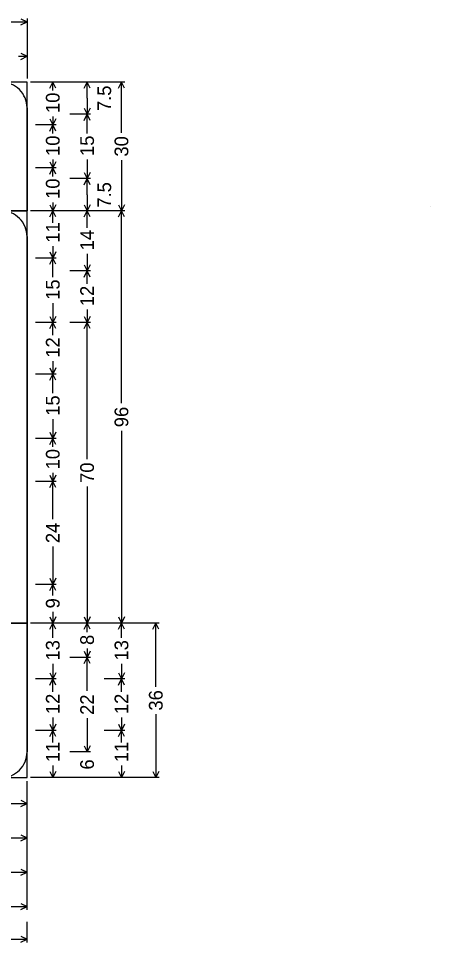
# Model space of a CAD drawing. Extents: x 667331 to 731245, y 738830 to 753817.
# Drawn here: x 720112.7 to 720256.7, y 747275.8 to 747598.6 of the extents above; entities that cross this region are included whole.
import ezdxf

# ---------------------------------------------------------------- set-up
doc = ezdxf.new("R2010")
doc.units = 0
doc.layers.add('R_SIGN', color=7, linetype='Continuous')

msp = doc.modelspace()

# ---------------------------------------------------------------- linework, layer by layer
at = {"layer": 'R_SIGN'}
for p, q in [((720113.54, 747598.51), (720115.68, 747597.43)), ((720115.68, 747598.63), (720115.68, 747577.63)), ((720027.67, 747597.43), (720115.68, 747597.43)), ((720113.54, 747596.36), (720115.68, 747597.43)), ((720112.71, 747585.43), (720115.68, 747585.43)), ((720113.54, 747586.51), (720115.68, 747585.43)), ((720113.54, 747584.36), (720115.68, 747585.43)), ((720115.68, 747586.63), (720115.68, 747579.43)), ((720149.88, 747576.43), (720116.88, 747576.43)), ((720125.88, 747576.43), (720118.68, 747576.43)), ((720123.61, 747574.29), (720124.68, 747576.43)), ((720124.68, 747573.46), (720124.68, 747576.43)), ((720125.76, 747574.29), (720124.68, 747576.43)), ((720137.88, 747576.43), (720130.68, 747576.43)), ((720135.61, 747574.29), (720136.68, 747576.43)), ((720136.68, 747570.81), (720136.68, 747576.43)), ((720137.76, 747574.29), (720136.68, 747576.43)), ((720147.61, 747574.29), (720148.68, 747576.43)), ((720148.68, 747558.68), (720148.68, 747576.43)), ((720149.76, 747574.29), (720148.68, 747576.43)), ((720136.68, 747570.81), (720136.68, 747565.18)), ((720135.61, 747567.33), (720136.68, 747565.18)), ((720137.76, 747567.33), (720136.68, 747565.18)), ((720123.61, 747563.58), (720124.68, 747561.43)), ((720124.68, 747564.4), (720124.68, 747561.43)), ((720125.76, 747563.58), (720124.68, 747561.43)), ((720137.88, 747565.18), (720130.68, 747565.18)), ((720135.61, 747563.04), (720136.68, 747565.18)), ((720136.68, 747558.48), (720136.68, 747565.18)), ((720137.76, 747563.04), (720136.68, 747565.18)), ((720125.88, 747561.43), (720118.68, 747561.43)), ((720123.61, 747559.29), (720124.68, 747561.43)), ((720124.68, 747558.46), (720124.68, 747561.43)), ((720125.76, 747559.29), (720124.68, 747561.43)), ((720123.61, 747548.58), (720124.68, 747546.43)), ((720124.68, 747549.4), (720124.68, 747546.43)), ((720125.76, 747548.58), (720124.68, 747546.43)), ((720136.68, 747549.39), (720136.68, 747542.68)), ((720148.68, 747549.19), (720148.68, 747531.43)), ((720125.88, 747546.43), (720118.68, 747546.43)), ((720125.88, 747546.43), (720118.68, 747546.43)), ((720123.61, 747544.29), (720124.68, 747546.43)), ((720124.68, 747543.46), (720124.68, 747546.43)), ((720125.76, 747544.29), (720124.68, 747546.43)), ((720135.61, 747544.83), (720136.68, 747542.68)), ((720137.76, 747544.83), (720136.68, 747542.68)), ((720137.88, 747542.68), (720130.68, 747542.68)), ((720137.88, 747542.68), (720130.68, 747542.68)), ((720135.61, 747540.54), (720136.68, 747542.68)), ((720136.68, 747537.06), (720136.68, 747542.68)), ((720137.76, 747540.54), (720136.68, 747542.68)), ((720136.68, 747537.06), (720136.68, 747531.43)), ((720124.68, 747534.4), (720124.68, 747531.43)), ((720149.88, 747531.43), (720116.88, 747531.43)), ((720149.88, 747531.43), (720116.88, 747531.43)), ((720125.88, 747531.43), (720118.68, 747531.43)), ((720125.88, 747531.43), (720118.68, 747531.43)), ((720123.61, 747533.58), (720124.68, 747531.43)), ((720123.61, 747529.29), (720124.68, 747531.43)), ((720125.76, 747533.58), (720124.68, 747531.43)), ((720124.68, 747527.24), (720124.68, 747531.43)), ((720125.76, 747529.29), (720124.68, 747531.43)), ((720137.88, 747531.43), (720130.68, 747531.43)), ((720137.88, 747531.43), (720130.68, 747531.43)), ((720135.61, 747533.58), (720136.68, 747531.43)), ((720135.61, 747529.29), (720136.68, 747531.43)), ((720137.76, 747533.58), (720136.68, 747531.43)), ((720136.68, 747525.45), (720136.68, 747531.43)), ((720137.76, 747529.29), (720136.68, 747531.43)), ((720147.61, 747533.58), (720148.68, 747531.43)), ((720147.61, 747529.29), (720148.68, 747531.43)), ((720149.76, 747533.58), (720148.68, 747531.43)), ((720148.68, 747464.23), (720148.68, 747531.43)), ((720149.76, 747529.29), (720148.68, 747531.43)), ((720256.68, 747532.93), (720256.68, 747532.93)), ((720256.68, 747532.93), (720256.68, 747532.93)), ((720256.68, 747532.93), (720256.68, 747532.93)), ((720256.68, 747532.93), (720256.68, 747532.93)), ((720124.68, 747519.13), (720124.68, 747514.93)), ((720125.88, 747514.93), (720118.68, 747514.93)), ((720123.61, 747517.08), (720124.68, 747514.93)), ((720123.61, 747512.79), (720124.68, 747514.93)), ((720125.76, 747517.08), (720124.68, 747514.93)), ((720124.68, 747508.23), (720124.68, 747514.93)), ((720125.76, 747512.79), (720124.68, 747514.93)), ((720136.68, 747516.42), (720136.68, 747510.43)), ((720135.61, 747512.58), (720136.68, 747510.43)), ((720137.76, 747512.58), (720136.68, 747510.43)), ((720137.88, 747510.43), (720130.68, 747510.43)), ((720135.61, 747508.29), (720136.68, 747510.43)), ((720136.68, 747505.95), (720136.68, 747510.43)), ((720137.76, 747508.29), (720136.68, 747510.43)), ((720124.68, 747499.14), (720124.68, 747492.43)), ((720136.68, 747496.92), (720136.68, 747492.43)), ((720125.88, 747492.43), (720118.68, 747492.43)), ((720123.61, 747494.58), (720124.68, 747492.43)), ((720123.61, 747490.29), (720124.68, 747492.43)), ((720125.76, 747494.58), (720124.68, 747492.43)), ((720124.68, 747487.95), (720124.68, 747492.43)), ((720125.76, 747490.29), (720124.68, 747492.43)), ((720137.88, 747492.43), (720130.68, 747492.43)), ((720137.88, 747492.43), (720130.68, 747492.43)), ((720135.61, 747494.58), (720136.68, 747492.43)), ((720135.61, 747490.29), (720136.68, 747492.43)), ((720137.76, 747494.58), (720136.68, 747492.43)), ((720136.68, 747444.68), (720136.68, 747492.43)), ((720137.76, 747490.29), (720136.68, 747492.43)), ((720124.68, 747478.92), (720124.68, 747474.43)), ((720123.61, 747476.58), (720124.68, 747474.43)), ((720125.76, 747476.58), (720124.68, 747474.43)), ((720125.88, 747474.43), (720118.68, 747474.43)), ((720123.61, 747472.29), (720124.68, 747474.43)), ((720124.68, 747467.73), (720124.68, 747474.43)), ((720125.76, 747472.29), (720124.68, 747474.43)), ((720124.68, 747458.64), (720124.68, 747451.93)), ((720123.61, 747454.08), (720124.68, 747451.93)), ((720125.76, 747454.08), (720124.68, 747451.93)), ((720148.68, 747454.64), (720148.68, 747387.43)), ((720125.88, 747451.93), (720118.68, 747451.93)), ((720123.61, 747449.79), (720124.68, 747451.93)), ((720124.68, 747448.96), (720124.68, 747451.93)), ((720125.76, 747449.79), (720124.68, 747451.93)), ((720123.61, 747439.08), (720124.68, 747436.93)), ((720124.68, 747439.9), (720124.68, 747436.93)), ((720125.76, 747439.08), (720124.68, 747436.93)), ((720125.88, 747436.93), (720118.68, 747436.93)), ((720123.61, 747434.79), (720124.68, 747436.93)), ((720124.68, 747423.71), (720124.68, 747436.93)), ((720125.76, 747434.79), (720124.68, 747436.93)), ((720136.68, 747435.19), (720136.68, 747387.43)), ((720124.68, 747414.15), (720124.68, 747400.93)), ((720123.61, 747403.08), (720124.68, 747400.93)), ((720125.76, 747403.08), (720124.68, 747400.93)), ((720125.88, 747400.93), (720118.68, 747400.93)), ((720125.88, 747400.93), (720118.68, 747400.93)), ((720123.61, 747398.79), (720124.68, 747400.93)), ((720124.68, 747397.03), (720124.68, 747400.93)), ((720125.76, 747398.79), (720124.68, 747400.93)), ((720123.61, 747389.58), (720124.68, 747387.43)), ((720124.68, 747391.34), (720124.68, 747387.43)), ((720125.76, 747389.58), (720124.68, 747387.43)), ((720135.61, 747389.58), (720136.68, 747387.43)), ((720137.76, 747389.58), (720136.68, 747387.43)), ((720147.61, 747389.58), (720148.68, 747387.43)), ((720149.76, 747389.58), (720148.68, 747387.43)), ((720149.88, 747387.43), (720116.88, 747387.43)), ((720161.88, 747387.43), (720116.88, 747387.43)), ((720125.88, 747387.43), (720118.68, 747387.43)), ((720125.88, 747387.43), (720118.68, 747387.43)), ((720123.61, 747385.29), (720124.68, 747387.43)), ((720124.68, 747382.23), (720124.68, 747387.43)), ((720125.76, 747385.29), (720124.68, 747387.43)), ((720137.88, 747387.43), (720130.68, 747387.43)), ((720137.88, 747387.43), (720130.68, 747387.43)), ((720135.61, 747385.29), (720136.68, 747387.43)), ((720136.68, 747384.29), (720136.68, 747387.43)), ((720137.76, 747385.29), (720136.68, 747387.43)), ((720149.88, 747387.43), (720142.68, 747387.43)), ((720147.61, 747385.29), (720148.68, 747387.43)), ((720148.68, 747382.23), (720148.68, 747387.43)), ((720149.76, 747385.29), (720148.68, 747387.43)), ((720159.61, 747385.29), (720160.68, 747387.43)), ((720160.68, 747365.21), (720160.68, 747387.43)), ((720161.76, 747385.29), (720160.68, 747387.43)), ((720135.61, 747377.58), (720136.68, 747375.43)), ((720136.68, 747378.57), (720136.68, 747375.43)), ((720137.76, 747377.58), (720136.68, 747375.43)), ((720124.68, 747373.14), (720124.68, 747367.93)), ((720137.88, 747375.43), (720130.68, 747375.43)), ((720135.61, 747373.29), (720136.68, 747375.43)), ((720136.68, 747363.71), (720136.68, 747375.43)), ((720137.76, 747373.29), (720136.68, 747375.43)), ((720148.68, 747373.14), (720148.68, 747367.93)), ((720123.61, 747370.08), (720124.68, 747367.93)), ((720125.76, 747370.08), (720124.68, 747367.93)), ((720147.61, 747370.08), (720148.68, 747367.93)), ((720149.76, 747370.08), (720148.68, 747367.93)), ((720125.88, 747367.93), (720118.68, 747367.93)), ((720123.61, 747365.79), (720124.68, 747367.93)), ((720124.68, 747363.45), (720124.68, 747367.93)), ((720125.76, 747365.79), (720124.68, 747367.93)), ((720149.88, 747367.93), (720142.68, 747367.93)), ((720147.61, 747365.79), (720148.68, 747367.93)), ((720148.68, 747363.45), (720148.68, 747367.93)), ((720149.76, 747365.79), (720148.68, 747367.93)), ((720124.68, 747354.42), (720124.68, 747349.93)), ((720136.68, 747354.15), (720136.68, 747342.43)), ((720148.68, 747354.42), (720148.68, 747349.93)), ((720160.68, 747355.65), (720160.68, 747333.43)), ((720125.88, 747349.93), (720118.68, 747349.93)), ((720125.88, 747349.93), (720118.68, 747349.93)), ((720123.61, 747352.08), (720124.68, 747349.93)), ((720123.61, 747347.79), (720124.68, 747349.93)), ((720125.76, 747352.08), (720124.68, 747349.93)), ((720124.68, 747345.74), (720124.68, 747349.93)), ((720125.76, 747347.79), (720124.68, 747349.93)), ((720149.88, 747349.93), (720142.68, 747349.93)), ((720149.88, 747349.93), (720142.68, 747349.93)), ((720147.61, 747352.08), (720148.68, 747349.93)), ((720147.61, 747347.79), (720148.68, 747349.93)), ((720149.76, 747352.08), (720148.68, 747349.93)), ((720148.68, 747345.74), (720148.68, 747349.93)), ((720149.76, 747347.79), (720148.68, 747349.93)), ((720135.61, 747344.58), (720136.68, 747342.43)), ((720137.76, 747344.58), (720136.68, 747342.43)), ((720137.88, 747342.43), (720130.68, 747342.43)), ((720137.88, 747342.43), (720130.68, 747342.43)), ((720124.68, 747337.63), (720124.68, 747333.43)), ((720148.68, 747337.63), (720148.68, 747333.43)), ((720123.61, 747335.58), (720124.68, 747333.43)), ((720125.76, 747335.58), (720124.68, 747333.43)), ((720147.61, 747335.58), (720148.68, 747333.43)), ((720149.76, 747335.58), (720148.68, 747333.43)), ((720159.61, 747335.58), (720160.68, 747333.43)), ((720161.76, 747335.58), (720160.68, 747333.43)), ((720115.68, 747287.23), (720115.68, 747332.23)), ((720115.68, 747323.23), (720115.68, 747330.43)), ((720161.88, 747333.43), (720116.88, 747333.43)), ((720125.88, 747333.43), (720118.68, 747333.43)), ((720137.88, 747333.43), (720130.68, 747333.43)), ((720149.88, 747333.43), (720142.68, 747333.43)), ((720071.95, 747324.43), (720115.68, 747324.43)), ((720113.54, 747325.51), (720115.68, 747324.43)), ((720113.54, 747323.36), (720115.68, 747324.43)), ((720115.68, 747311.23), (720115.68, 747318.43)), ((720106.48, 747312.43), (720115.68, 747312.43)), ((720113.54, 747313.51), (720115.68, 747312.43)), ((720113.54, 747311.36), (720115.68, 747312.43)), ((720115.68, 747299.23), (720115.68, 747306.43)), ((720113.54, 747301.51), (720115.68, 747300.43)), ((720108.97, 747300.43), (720115.68, 747300.43)), ((720113.54, 747299.36), (720115.68, 747300.43)), ((720113.54, 747289.51), (720115.68, 747288.43)), ((719978.12, 747288.43), (720115.68, 747288.43)), ((720113.54, 747287.36), (720115.68, 747288.43)), ((720115.68, 747275.83), (720115.68, 747283.03)), ((720105.57, 747277.03), (720115.68, 747277.03)), ((720113.54, 747278.11), (720115.68, 747277.03)), ((720113.54, 747275.96), (720115.68, 747277.03))]:
    msp.add_line(p, q, dxfattribs=at)
for points in [[(719926.68, 747531.43), (720115.68, 747531.43), (720115.68, 747576.43), (719926.68, 747576.43), (719926.68, 747531.43), (719926.68, 747531.43)], [(720115.68, 747567.43), (720115.68, 747531.43)], [(719827.68, 747387.43), (720115.68, 747387.43), (720115.68, 747531.43), (719827.68, 747531.43), (719827.68, 747387.43), (719827.68, 747387.43)], [(720115.68, 747522.43), (720115.68, 747387.43)], [(719827.68, 747333.43), (720115.68, 747333.43), (720115.68, 747387.43), (719827.68, 747387.43), (719827.68, 747333.43), (719827.68, 747333.43)], [(720115.68, 747387.43), (720115.68, 747342.43)]]:
    msp.add_lwpolyline(points, dxfattribs=at)
for centre, start, end in [((720106.68, 747567.43), 0, 90.0002), ((720106.68, 747522.43), 0, 90.0002), ((720106.68, 747342.43), 270.0001, 0.0003)]:
    msp.add_arc(centre, 9, start, end, dxfattribs=at)

# ---------------------------------------------------------------- texts
for s, p in [('7.5', (720145.08, 747566.28)), ('10', (720127.08, 747565.6)), ('10', (720127.08, 747550.6)), ('15', (720139.08, 747550.59)), ('30', (720151.08, 747550.39)), ('10', (720127.08, 747535.6)), ('7.5', (720145.08, 747532.53)), ('11', (720127.08, 747520.33)), ('14', (720139.08, 747517.62)), ('15', (720127.08, 747500.34)), ('12', (720139.08, 747498.12)), ('12', (720127.08, 747480.12)), ('15', (720127.08, 747459.84)), ('96', (720151.08, 747455.84)), ('10', (720127.08, 747441.1)), ('70', (720139.08, 747436.39)), ('24', (720127.08, 747415.35)), ('9', (720127.08, 747392.54)), ('8', (720139.08, 747379.77)), ('13', (720127.08, 747374.34)), ('13', (720151.08, 747374.34)), ('36', (720163.08, 747356.85)), ('12', (720127.08, 747355.62)), ('22', (720139.08, 747355.35)), ('12', (720151.08, 747355.62)), ('11', (720127.08, 747338.83)), ('11', (720151.08, 747338.83)), ('6', (720139.08, 747336.25))]:
    msp.add_text(s, height=4.8, rotation=90.0002, dxfattribs=at).set_placement(p)

doc.saveas('drawing.dxf')
